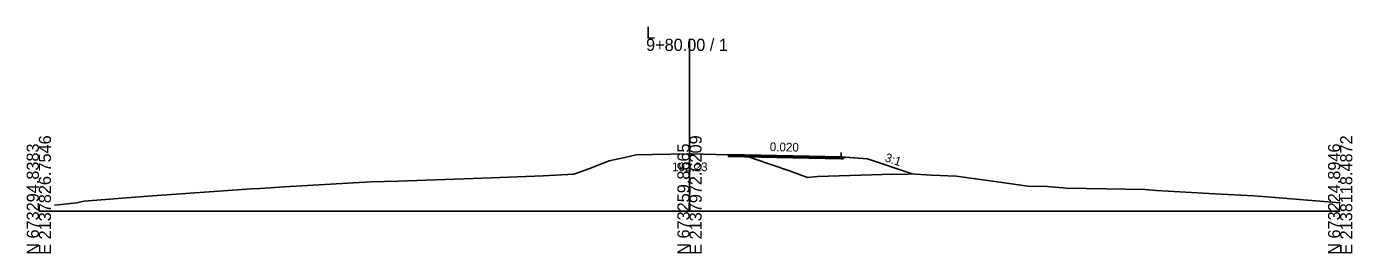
# Model space of a CAD drawing. Extents: x -26 to 5503, y -10 to 7033.
# Drawn here: x 2597.2 to 2902.8, y -9.7 to 42.5 of the extents above; entities that cross this region are included whole.
import ezdxf

# ---------------------------------------------------------------- set-up
doc = ezdxf.new("R2010")
doc.units = 0
for name, color, linetype in [('Exist Cross Section Cell', 7, 'Continuous'), ('Exist XS Center Line Elevation Label', 7, 'Continuous'), ('Exist XS Ground Line', 7, 'Continuous'), ('Prop CMT Pvmt Course 1', 7, 'Continuous'), ('Prop CMT Pvmt Course 2', 7, 'Continuous'), ('Prop CMT Pvmt Surface', 7, 'Continuous'), ('Prop CMT Pvmt Surface Shoulder', 7, 'Continuous'), ('Prop CMT Shld Paved Course 1', 7, 'Continuous'), ('Prop CMT Shld Paved Course 2', 7, 'Continuous'), ('Prop CMT Slope Grass', 7, 'Continuous'), ('Prop CMT Subgrade Earthwork', 7, 'Continuous'), ('Prop XS Earthwork Shape', 7, 'Continuous'), ('Prop XS EOT Tick Mark', 7, 'Continuous'), ('Prop XS SE Text', 7, 'Continuous'), ('Prop XS Side Slope Text', 7, 'Continuous')]:
    doc.layers.add(name, color=color, linetype=linetype)

msp = doc.modelspace()

# ---------------------------------------------------------------- linework, layer by layer
at = {"layer": 'Exist Cross Section Cell'}
for p, q in [((2750, 0), (2750, 39.71)), ((2600, 0), (2750, 0)), ((2750, 0), (2900, 0))]:
    msp.add_line(p, q, dxfattribs=at)
at = {"layer": 'Exist XS Ground Line'}
for p, q in [((2733.63, 12.09), (2735.09, 12.35)), ((2735.09, 12.35), (2737.7, 12.98)), ((2737.7, 12.98), (2741.44, 13.05)), ((2741.44, 13.05), (2750, 13.23)), ((2750, 13.23), (2750.44, 13.24)), ((2750.44, 13.24), (2758.81, 13.03)), ((2758.81, 13.03), (2761.94, 12.94)), ((2761.94, 12.94), (2763.48, 12.63)), ((2763.48, 12.63), (2764.9, 12.06)), ((2723.37, 8.58), (2726.79, 9.77)), ((2726.79, 9.77), (2731.47, 11.64)), ((2731.47, 11.64), (2733.63, 12.09)), ((2764.9, 12.06), (2773.06, 9.34)), ((2773.06, 9.34), (2777.19, 7.78)), ((2656.66, 5.6), (2676.54, 6.77)), ((2676.54, 6.77), (2682.8, 6.97)), ((2682.8, 6.97), (2702.25, 7.6)), ((2702.25, 7.6), (2716.28, 8.2)), ((2716.28, 8.2), (2723.37, 8.58)), ((2777.19, 7.78), (2779.58, 8.04)), ((2779.58, 8.04), (2796.85, 8.57)), ((2796.85, 8.57), (2799.91, 8.47)), ((2799.91, 8.47), (2800.77, 8.64)), ((2800.77, 8.64), (2805.81, 8.28)), ((2805.81, 8.28), (2811.46, 8.05)), ((2811.46, 8.05), (2822.61, 6.52)), ((2822.61, 6.52), (2827.99, 5.79)), ((2610.48, 2.31), (2625.12, 3.52)), ((2625.12, 3.52), (2648.99, 5.21)), ((2648.99, 5.21), (2650.96, 5.26)), ((2650.96, 5.26), (2656.66, 5.6)), ((2827.99, 5.79), (2832.54, 5.7)), ((2832.54, 5.7), (2836.9, 5.31)), ((2836.9, 5.31), (2855.04, 5.05)), ((2855.04, 5.05), (2857.63, 4.79)), ((2857.63, 4.79), (2871.12, 4.03)), ((2871.12, 4.03), (2880.06, 3.58)), ((2880.06, 3.58), (2882.21, 3.43)), ((2882.21, 3.43), (2900, 1.98)), ((2603.63, 1.41), (2605.2, 1.57)), ((2605.2, 1.57), (2608.65, 1.95)), ((2608.65, 1.95), (2610.48, 2.31))]:
    msp.add_line(p, q, dxfattribs=at)
at = {"layer": 'Prop CMT Pvmt Course 1'}
for points in [[(2759, 13.05), (2785, 12.53)], [(2759, 12.94), (2759, 13.05)], [(2785, 12.42), (2759, 12.94)], [(2785, 12.53), (2785, 12.42)]]:
    msp.add_lwpolyline(points, dxfattribs=at)
at = {"layer": 'Prop CMT Pvmt Course 2'}
for p, q in [((2759, 12.61), (2759, 12.94)), ((2785, 12.09), (2759, 12.61))]:
    msp.add_line(p, q, dxfattribs=at)
for points in [[(2759, 12.94), (2785, 12.42)], [(2785, 12.42), (2785, 12.09)]]:
    msp.add_lwpolyline(points, dxfattribs=at)
at = {"layer": 'Prop CMT Pvmt Surface'}
msp.add_line((2759, 13.05), (2758.99, 13.02), dxfattribs=at)
msp.add_lwpolyline([(2759, 13.05), (2785, 12.53)], dxfattribs=at)
at = {"layer": 'Prop CMT Pvmt Surface Shoulder'}
msp.add_lwpolyline([(2785, 12.53), (2785, 12.53)], dxfattribs=at)
at = {"layer": 'Prop CMT Shld Paved Course 1'}
for points in [[(2785, 12.53), (2785, 12.53)], [(2785, 12.53), (2785.11, 12.42)], [(2785, 12.42), (2785, 12.53)], [(2785.11, 12.42), (2785, 12.42)]]:
    msp.add_lwpolyline(points, dxfattribs=at)
at = {"layer": 'Prop CMT Shld Paved Course 2'}
for points in [[(2785, 12.42), (2785.11, 12.42)], [(2785, 12.09), (2785, 12.42)], [(2785.11, 12.42), (2785.11, 12.42)], [(2785.11, 12.42), (2785.45, 12.08)], [(2785.45, 12.08), (2785, 12.09)]]:
    msp.add_lwpolyline(points, dxfattribs=at)
at = {"layer": 'Prop CMT Slope Grass'}
for points in [[(2785, 12.53), (2791, 12.05)], [(2791, 12.05), (2801.35, 8.6)]]:
    msp.add_lwpolyline(points, dxfattribs=at)
at = {"layer": 'Prop CMT Subgrade Earthwork'}
for points in [[(2758.99, 13.02), (2759, 12.61), (2785, 12.09)], [(2785.45, 12.08), (2785.83, 12.46)], [(2785, 12.09), (2785.45, 12.08)]]:
    msp.add_lwpolyline(points, dxfattribs=at)
at = {"layer": 'Prop XS Earthwork Shape'}
for points in [[(2759, 13.05), (2761.94, 12.94), (2763.48, 12.63), (2763.77, 12.52), (2759, 12.61)], [(2763.77, 12.52), (2764.9, 12.06), (2773.06, 9.34), (2777.19, 7.78), (2779.58, 8.04), (2796.85, 8.57), (2799.91, 8.47), (2800.77, 8.64), (2801.35, 8.6), (2791, 12.05), (2785.83, 12.46), (2785.45, 12.08), (2785, 12.09)]]:
    msp.add_lwpolyline(points, close=True, dxfattribs=at)
at = {"layer": 'Prop XS EOT Tick Mark'}
msp.add_lwpolyline([(2785, 12.53), (2785, 13.53)], dxfattribs=at)

# ---------------------------------------------------------------- texts
at = {"layer": 'Exist Cross Section Cell'}
for s, p in [('9+80.00 / 1', (2740, 36.91)), ('L', (2740, 39.71))]:
    msp.add_text(s, height=2.8, dxfattribs=at).set_placement(p)
for s, p in [('N 673294.8383', (2600, -10)), ('E 2137826.7546', (2602.8, -10)), ('N 673259.8665', (2750, -10)), ('E 2137972.6209', (2752.8, -10)), ('N 673224.8946', (2900, -10)), ('E 2138118.4872', (2902.8, -10))]:
    msp.add_text(s, height=2.8, rotation=90, dxfattribs=at).set_placement(p)
at = {"layer": 'Exist XS Center Line Elevation Label'}
msp.add_text('192.23', height=2, dxfattribs=at).set_placement((2745.99, 9.23))
at = {"layer": 'Prop XS SE Text'}
msp.add_text('0.020', height=2, rotation=358.8542, dxfattribs=at).set_placement((2768.49, 13.86))
at = {"layer": 'Prop XS Side Slope Text'}
msp.add_text('3:1', height=2, rotation=341.5651, dxfattribs=at).set_placement((2794.89, 11.54))

doc.saveas('drawing.dxf')
